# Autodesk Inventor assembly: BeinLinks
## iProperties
Author: Standard
Created: 2002-11
Part Number: BeinLinks
Document SubType Name: Baugruppe
Designer: Standard
Control State: 0
Master: False
Checked Out: False
PropertySet Name: Design Tracking Control
Shininess: 20.0
Angle Display Precision: 2
Document Length Units: 11269
Document Angle Units: 11283
Document Time Units: 11279
Document Mass Units: 11290
Document Length Units Precision: 3
Document Angle Units Precision: 2
Compacted: False
PropertySet Name: _Private Model Information
Density: 0.0
Volumn: 0.0
Area: 0.0
PropertySet Name: Model Information
